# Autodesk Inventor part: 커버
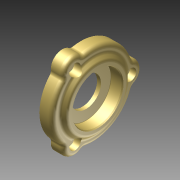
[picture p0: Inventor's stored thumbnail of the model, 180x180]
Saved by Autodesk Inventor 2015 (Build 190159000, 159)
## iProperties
Created: 2026-04
Part Number: 커버
Material: 일반
Document SubType Name: Modeling
Designer: User
Density: 1 g/cm^3
Appearance: 기본값
Author: User
Author: jhkim
Creation Date: 2026-03-26
Sending System: Autodesk Inventor 2026
Preprocessor: ST-DEVELOPER v20.1
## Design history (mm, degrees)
node "커버1"
node "솔리드1"
node "기준1"
